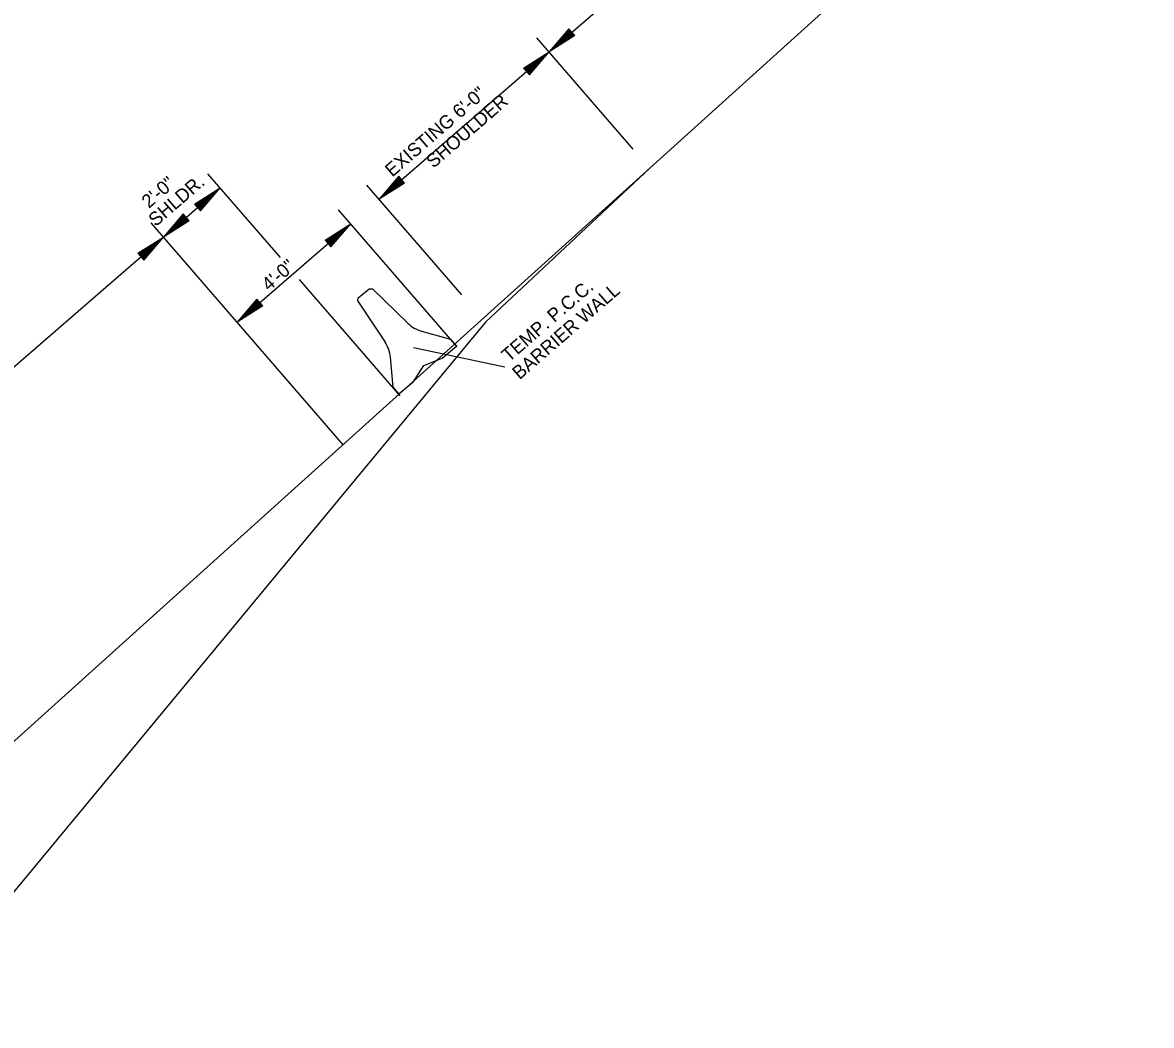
# Model space of a CAD drawing. Extents: x 192699 to 285914, y 194342 to 233219.
# Drawn here: x 262787.62 to 262817.71, y 213636.76 to 213663.47 of the extents above; entities that cross this region are included whole.
import ezdxf

# ---------------------------------------------------------------- set-up
doc = ezdxf.new("R2010")
doc.units = 0
doc.layers.add('TYPICAL SECTION FOR MOT', color=7, linetype='Continuous')

msp = doc.modelspace()

# ---------------------------------------------------------------- linework, layer by layer
at = {"layer": 'TYPICAL SECTION FOR MOT'}
for p, q in [((262801.659, 213662.693), (262813, 213672.51)), ((262817.71, 213671.653), (262804.337, 213659.599)), ((262802.185, 213663.307), (262801.659, 213662.693)), ((262802.199, 213663.292), (262801.76, 213662.78)), ((262802.212, 213663.276), (262801.864, 213662.87)), ((262802.225, 213663.261), (262801.965, 213662.957)), ((262802.238, 213663.246), (262802.067, 213663.046)), ((262802.289, 213663.187), (262802.067, 213663.046)), ((262802.252, 213663.23), (262802.168, 213663.134)), ((262802.276, 213663.202), (262802.168, 213663.134)), ((262802.343, 213663.126), (262802.185, 213663.307)), ((262803.9, 213660.104), (262801.332, 213663.071)), ((262802.343, 213663.126), (262801.659, 213662.693)), ((262802.329, 213663.141), (262801.76, 213662.78)), ((262802.316, 213663.156), (262801.864, 213662.87)), ((262802.303, 213663.171), (262801.965, 213662.957)), ((262797.123, 213658.766), (262801.659, 213662.693)), ((262800.976, 213662.26), (262801.659, 213662.693)), ((262800.989, 213662.245), (262801.558, 213662.605)), ((262801.12, 213662.093), (262801.558, 213662.605)), ((262801.133, 213662.078), (262801.659, 213662.693)), ((262801.002, 213662.229), (262801.454, 213662.515)), ((262801.015, 213662.214), (262801.353, 213662.428)), ((262801.029, 213662.198), (262801.251, 213662.339)), ((262801.08, 213662.139), (262801.251, 213662.339)), ((262801.093, 213662.124), (262801.353, 213662.428)), ((262801.106, 213662.109), (262801.454, 213662.515)), ((262800.976, 213662.26), (262801.133, 213662.078)), ((262801.042, 213662.183), (262801.15, 213662.252)), ((262801.067, 213662.155), (262801.15, 213662.252)), ((262804.337, 213659.599), (262780.377, 213638.004)), ((262804.337, 213659.599), (262799.958, 213655.491)), ((262794.498, 213657.215), (262792.564, 213659.448)), ((262797.649, 213659.38), (262797.123, 213658.766)), ((262797.662, 213659.365), (262797.224, 213658.853)), ((262797.676, 213659.349), (262797.328, 213658.943)), ((262797.689, 213659.334), (262797.429, 213659.03)), ((262797.702, 213659.319), (262797.531, 213659.119)), ((262797.715, 213659.303), (262797.632, 213659.206)), ((262797.74, 213659.275), (262797.632, 213659.206)), ((262797.806, 213659.198), (262797.649, 213659.38)), ((262791.379, 213657.761), (262792.891, 213659.07)), ((262792.208, 213658.637), (262792.891, 213659.07)), ((262792.221, 213658.622), (262792.79, 213658.983)), ((262792.352, 213658.471), (262792.79, 213658.983)), ((262792.365, 213658.456), (262792.891, 213659.07)), ((262799.328, 213656.219), (262796.796, 213659.144)), ((262797.806, 213659.198), (262797.123, 213658.766)), ((262797.793, 213659.214), (262797.224, 213658.853)), ((262797.78, 213659.229), (262797.328, 213658.943)), ((262797.767, 213659.244), (262797.429, 213659.03)), ((262797.753, 213659.26), (262797.531, 213659.119)), ((262792.234, 213658.607), (262792.686, 213658.893)), ((262792.247, 213658.592), (262792.585, 213658.805)), ((262792.261, 213658.576), (262792.483, 213658.717)), ((262792.312, 213658.517), (262792.483, 213658.717)), ((262792.325, 213658.501), (262792.585, 213658.805)), ((262792.338, 213658.486), (262792.686, 213658.893)), ((262791.905, 213658.375), (262791.379, 213657.761)), ((262792.063, 213658.194), (262791.905, 213658.375)), ((262792.208, 213658.637), (262792.365, 213658.456)), ((262792.274, 213658.561), (262792.382, 213658.629)), ((262792.299, 213658.532), (262792.382, 213658.629)), ((262799.202, 213654.836), (262796.04, 213658.489)), ((262796.178, 213652.218), (262791.052, 213658.139)), ((262792.063, 213658.194), (262791.379, 213657.761)), ((262791.919, 213658.36), (262791.48, 213657.849)), ((262792.049, 213658.209), (262791.48, 213657.849)), ((262791.932, 213658.345), (262791.584, 213657.939)), ((262792.036, 213658.225), (262791.584, 213657.939)), ((262791.945, 213658.33), (262791.685, 213658.026)), ((262792.023, 213658.24), (262791.685, 213658.026)), ((262791.958, 213658.314), (262791.787, 213658.115)), ((262792.009, 213658.255), (262791.787, 213658.115)), ((262791.972, 213658.299), (262791.888, 213658.202)), ((262791.996, 213658.27), (262791.888, 213658.202)), ((262793.343, 213655.493), (262796.367, 213658.111)), ((262795.684, 213657.678), (262796.367, 213658.111)), ((262795.841, 213657.497), (262796.367, 213658.111)), ((262795.697, 213657.663), (262796.266, 213658.024)), ((262795.71, 213657.648), (262796.162, 213657.934)), ((262795.723, 213657.632), (262796.061, 213657.846)), ((262795.801, 213657.542), (262796.061, 213657.846)), ((262795.814, 213657.527), (262796.162, 213657.934)), ((262795.827, 213657.512), (262796.266, 213658.024)), ((262780.038, 213647.943), (262791.379, 213657.761)), ((262790.696, 213657.328), (262791.379, 213657.761)), ((262790.709, 213657.313), (262791.278, 213657.674)), ((262790.722, 213657.298), (262791.174, 213657.584)), ((262790.735, 213657.283), (262791.073, 213657.496)), ((262790.813, 213657.192), (262791.073, 213657.496)), ((262790.826, 213657.177), (262791.174, 213657.584)), ((262790.84, 213657.162), (262791.278, 213657.674)), ((262790.853, 213657.147), (262791.379, 213657.761)), ((262795.684, 213657.678), (262795.841, 213657.497)), ((262795.737, 213657.617), (262795.959, 213657.758)), ((262795.75, 213657.602), (262795.858, 213657.67)), ((262795.774, 213657.573), (262795.858, 213657.67)), ((262795.788, 213657.558), (262795.959, 213657.758)), ((262790.696, 213657.328), (262790.853, 213657.147)), ((262790.749, 213657.267), (262790.971, 213657.408)), ((262790.762, 213657.252), (262790.87, 213657.32)), ((262790.787, 213657.223), (262790.87, 213657.32)), ((262790.8, 213657.208), (262790.971, 213657.408)), ((262797.69, 213653.527), (262795, 213656.634)), ((262796.57, 213656.143), (262796.859, 213656.382)), ((262796.859, 213656.382), (262796.952, 213656.379)), ((262796.952, 213656.379), (262797.893, 213655.462)), ((262793.869, 213656.107), (262793.343, 213655.493)), ((262793.882, 213656.092), (262793.444, 213655.58)), ((262793.895, 213656.077), (262793.548, 213655.67)), ((262793.909, 213656.062), (262793.648, 213655.758)), ((262793.987, 213655.971), (262793.648, 213655.758)), ((262793.922, 213656.046), (262793.751, 213655.846)), ((262793.973, 213655.987), (262793.751, 213655.846)), ((262793.935, 213656.031), (262793.852, 213655.934)), ((262793.96, 213656.002), (262793.852, 213655.934)), ((262794.026, 213655.926), (262793.869, 213656.107)), ((262796.557, 213656.051), (262796.57, 213656.143)), ((262796.557, 213656.051), (262797.287, 213654.958)), ((262794.026, 213655.926), (262793.343, 213655.493)), ((262794.013, 213655.941), (262793.444, 213655.58)), ((262794, 213655.956), (262793.548, 213655.67)), ((262799.958, 213655.491), (262784.431, 213636.758)), ((262798.255, 213655.255), (262799.029, 213655.043)), ((262800.472, 213654.291), (262798.042, 213654.81)), ((262798.804, 213654.532), (262799.188, 213654.851)), ((262799.029, 213655.043), (262799.188, 213654.851)), ((262797.424, 213654.564), (262797.491, 213653.765)), ((262798.313, 213654.34), (262798.804, 213654.532)), ((262798.035, 213653.892), (262798.313, 213654.34)), ((262798.035, 213653.892), (262797.65, 213653.573)), ((262797.491, 213653.765), (262797.65, 213653.573))]:
    msp.add_line(p, q, dxfattribs=at)
for centre, start, end in [((262798.475, 213656.059), 225.7465, 254.7295), ((262796.594, 213654.495), 4.7455, 33.7285)]:
    msp.add_arc(centre, 0.833, start, end, dxfattribs=at)

# ---------------------------------------------------------------- texts
for s, p in [('EXISTING 6\'-0"', (262797.476, 213659.343)), ('SHOULDER', (262798.573, 213659.578)), ('2\'-0"', (262790.989, 213658.509)), ('SHLDR.', (262791.172, 213658.023)), ('4\'-0"', (262794.189, 213656.303)), ('TEMP. P.C.C.', (262800.585, 213654.415)), ('BARRIER WALL', (262800.867, 213653.945))]:
    msp.add_text(s, height=0.36, rotation=40.8833, dxfattribs=at).set_placement(p)

doc.saveas('drawing.dxf')
